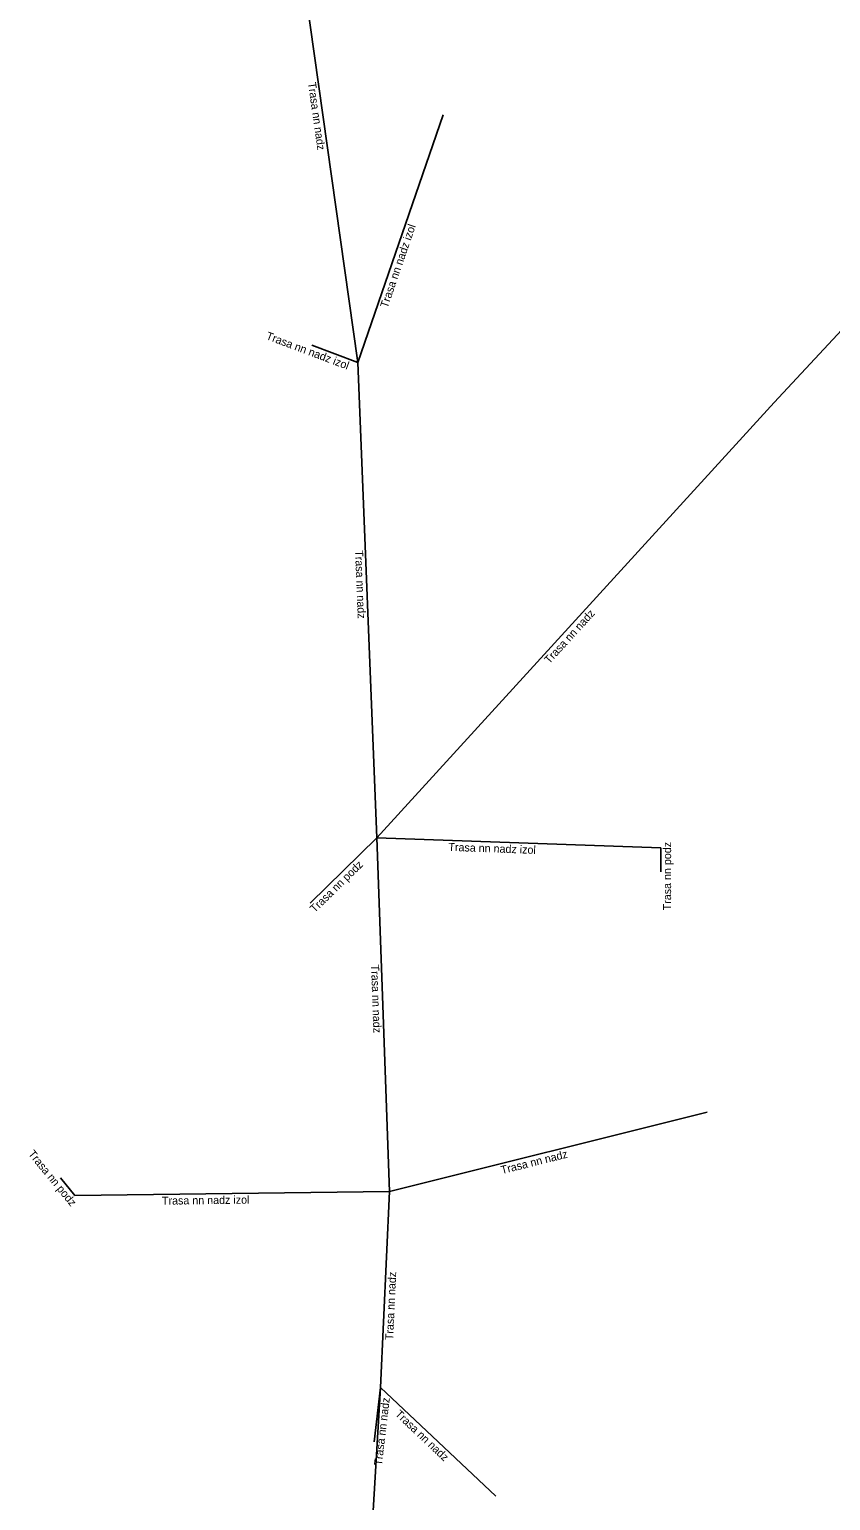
# Model space of a CAD drawing. Extents: x -747466 to -746981, y -1017505 to -1017087.
# Drawn here: x -747366 to -747316, y -1017425.2 to -1017333.3 of the extents above; entities that cross this region are included whole.
import ezdxf

# ---------------------------------------------------------------- set-up
doc = ezdxf.new("R2010")
doc.units = 0
doc.layers.add('Popiskový text - Ostatní atributy Trasy', color=7, linetype='Continuous')
doc.layers.add('Spojnice NN', color=7, linetype='Continuous')

msp = doc.modelspace()

# ---------------------------------------------------------------- linework, layer by layer
at = {"layer": 'Spojnice NN'}
for points in [[(-747349.595, -1017325.176), (-747345.515, -1017354.084)], [(-747300.334, -1017335.974), (-747319.51, -1017356.568)], [(-747345.515, -1017354.084), (-747340.2, -1017338.6)], [(-747345.515, -1017354.084), (-747348.4, -1017353)], [(-747345.515, -1017354.084), (-747344.325, -1017383.771)], [(-747344.325, -1017383.771), (-747319.51, -1017356.568)], [(-747344.325, -1017383.771), (-747348.509, -1017387.854)], [(-747344.325, -1017383.771), (-747343.547, -1017405.86)], [(-747344.325, -1017383.771), (-747326.6, -1017384.4)], [(-747326.6, -1017384.4), (-747326.602, -1017385.9)], [(-747323.7, -1017400.9), (-747343.547, -1017405.86)], [(-747363.2, -1017406.1), (-747364.1, -1017405)], [(-747363.2, -1017406.1), (-747343.547, -1017405.86)], [(-747343.547, -1017405.86), (-747344.1, -1017418.1)], [(-747344.1, -1017418.1), (-747345.1, -1017434.9)], [(-747344.1, -1017418.1), (-747344.5, -1017421.5)], [(-747344.1, -1017418.1), (-747336.9, -1017424.9)]]:
    msp.add_lwpolyline(points, dxfattribs=at)

# ---------------------------------------------------------------- texts
at = {"layer": 'Popiskový text - Ostatní atributy Trasy'}
for s, rotation, p in [('Trasa nn nadz', 278.03352, (-747348.638, -1017336.604)), ('Trasa nn nadz izol', 71.05483, (-747343.668, -1017350.705)), ('Trasa nn nadz izol', 339.40696, (-747351.295, -1017352.606)), ('Trasa nn nadz', 272.29547, (-747345.696, -1017365.809)), ('Trasa nn nadz', 47.62844, (-747333.559, -1017372.933)), ('Trasa nn nadz izol', 357.96762, (-747339.873, -1017384.579)), ('Trasa nn podz', 89.9427, (-747325.954, -1017388.298)), ('Trasa nn podz', 44.30004, (-747348.216, -1017388.476)), ('Trasa nn nadz', 272.01719, (-747344.697, -1017391.693)), ('Trasa nn podz', 309.28941, (-747366.147, -1017403.525)), ('Trasa nn nadz', 14.03149, (-747336.52, -1017404.774)), ('Trasa nn nadz izol', 0.69965, (-747357.755, -1017406.684)), ('Trasa nn nadz', 87.41315, (-747343.316, -1017415.154)), ('Trasa nn nadz', 83.29016, (-747344.022, -1017423.002)), ('Trasa nn nadz', 316.63658, (-747343.235, -1017419.812))]:
    msp.add_text(s, height=0.5, rotation=rotation, dxfattribs=at).set_placement(p)

doc.saveas('drawing.dxf')
